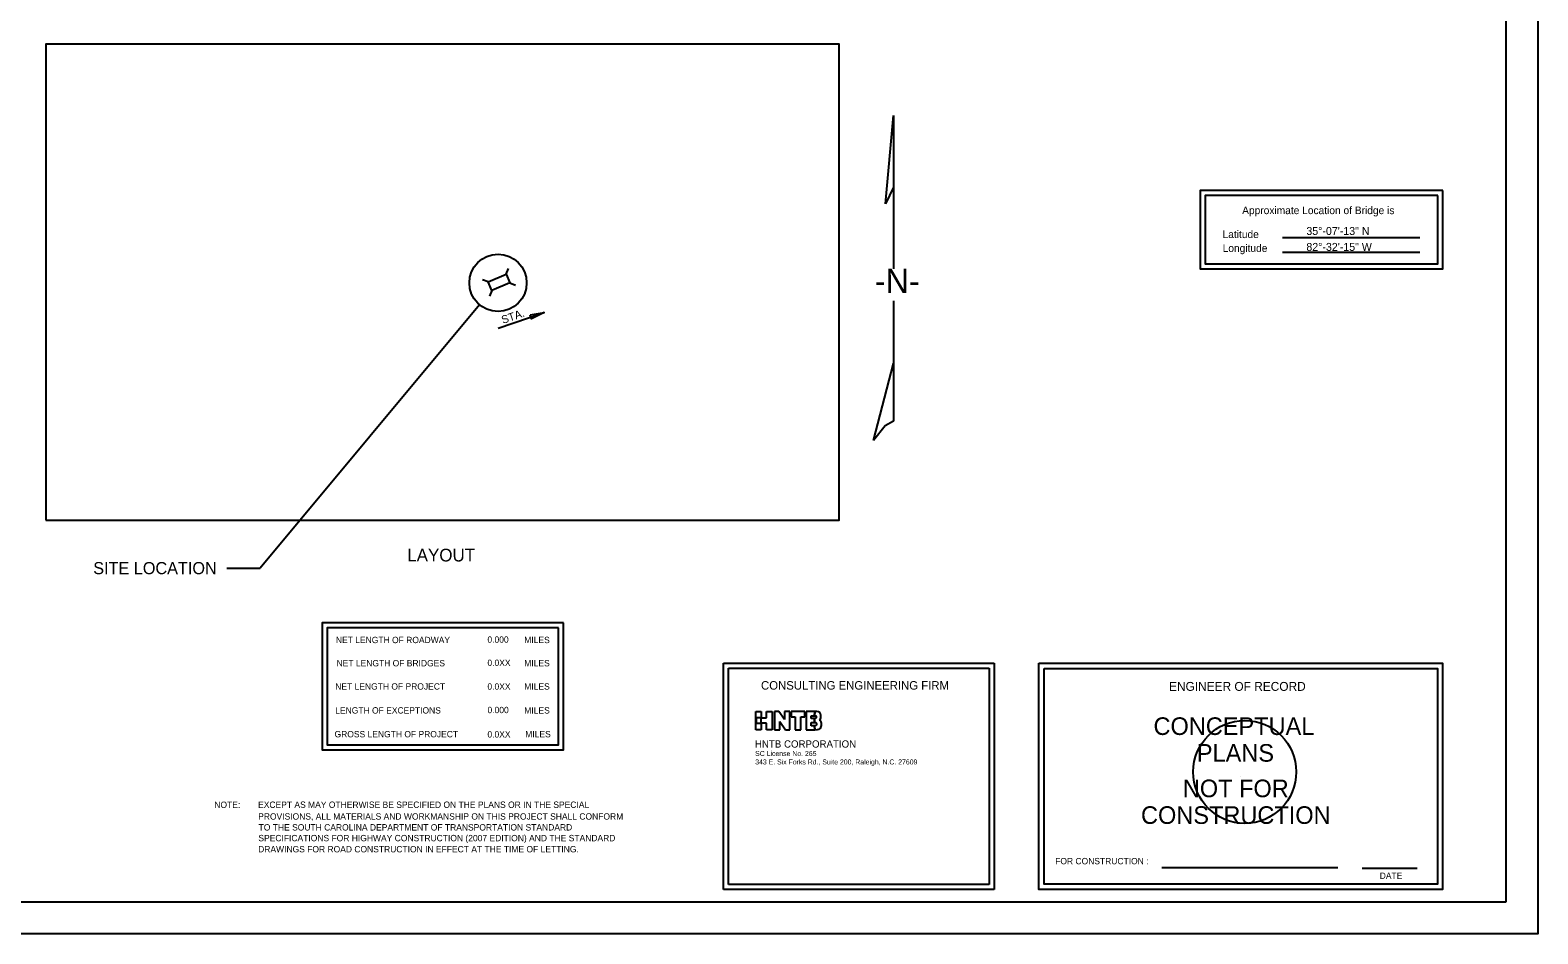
# Model space of a CAD drawing. Extents: x 0 to 4.05, y -2.5 to 2.32.
# Drawn here: x 1.021 to 3, y -2.5 to -1.314 of the extents above; entities that cross this region are included whole.
import ezdxf

# ---------------------------------------------------------------- set-up
doc = ezdxf.new("R2010")
doc.units = 0
for name, color, linetype in [('BR_AUTO DIMENSION', 7, 'Continuous'), ('BR_BORDER LINES', 7, 'Continuous'), ('BR_DETAILS', 7, 'Continuous'), ('BR_TEXT', 7, 'Continuous'), ('Default', 7, 'Continuous'), ('NoPlot', 7, 'Continuous'), ('V7_23', 7, 'Continuous')]:
    doc.layers.add(name, color=color, linetype=linetype)

msp = doc.modelspace()

# ---------------------------------------------------------------- linework, layer by layer
at = {"layer": 'BR_AUTO DIMENSION'}
for p, q in [((2.1436, -1.5418), (2.1542, -1.4259)), ((2.1542, -1.4259), (2.1542, -1.5203)), ((2.1542, -1.5203), (2.1436, -1.5418)), ((2.1542, -1.5203), (2.1542, -1.5857)), ((2.1542, -1.5857), (2.1542, -1.6274)), ((1.6107, -1.6746), (1.3227, -2.02)), ((2.1542, -1.6691), (2.1542, -1.7516)), ((2.1279, -1.8526), (2.1542, -1.7516)), ((2.1542, -1.7516), (2.1542, -1.7641)), ((2.1542, -1.7641), (2.1542, -1.8273)), ((1.2789, -2.02), (1.3227, -2.02)), ((1.931, -2.1449), (2.286, -2.1449)), ((1.931, -2.4416), (1.931, -2.1449)), ((1.9373, -2.1513), (2.2796, -2.1513)), ((1.9373, -2.4352), (1.9373, -2.1513)), ((2.2796, -2.1513), (2.2796, -2.4352)), ((2.286, -2.1449), (2.286, -2.4416)), ((2.286, -2.4416), (1.931, -2.4416)), ((2.2796, -2.4352), (1.9373, -2.4352))]:
    msp.add_line(p, q, dxfattribs=at)
msp.add_lwpolyline([(2.1542, -1.8273), (2.1429, -1.8334), (2.1279, -1.8526)], dxfattribs=at)
msp.add_circle((1.6348, -1.6457), 0.0376, dxfattribs=at)
at = {"layer": 'BR_BORDER LINES'}
for p, q in [((2.9583, -2.4582), (2.9583, -0.7082)), ((2.9583, -1.3928), (2.9583, -0.8053)), ((0.1667, -2.4582), (2.9583, -2.4582))]:
    msp.add_line(p, q, dxfattribs=at)
msp.add_lwpolyline([(1.0411, -1.9573), (2.0828, -1.9573), (2.0828, -1.3323), (1.0411, -1.3323)], close=True, dxfattribs=at)
at = {"layer": 'BR_DETAILS'}
for p, q in [((2.6649, -1.5862), (2.8452, -1.5862)), ((2.6649, -1.6056), (2.8452, -1.6056)), ((2.5063, -2.4129), (2.7373, -2.4129)), ((2.7692, -2.4138), (2.8416, -2.4138))]:
    msp.add_line(p, q, dxfattribs=at)
for points in [[(2.8752, -1.5246), (2.5568, -1.5246), (2.5568, -1.6272), (2.8752, -1.6272)], [(2.8685, -1.5312), (2.5634, -1.5312), (2.5634, -1.6206), (2.8685, -1.6206)], [(2.345, -2.1449), (2.875, -2.1449), (2.875, -2.4416), (2.345, -2.4416)], [(2.3517, -2.1516), (2.8683, -2.1516), (2.8683, -2.4349), (2.3517, -2.4349)]]:
    msp.add_lwpolyline(points, close=True, dxfattribs=at)
at = {"layer": 'BR_TEXT'}
for p, q in [((1.6219, -1.6444), (1.6143, -1.6415)), ((1.6455, -1.6344), (1.6487, -1.6269)), ((1.6267, -1.6558), (1.6235, -1.6632)), ((1.6503, -1.6458), (1.6579, -1.6486)), ((1.6348, -1.7053), (1.6955, -1.6844))]:
    msp.add_line(p, q, dxfattribs=at)
for points in [[(1.6455, -1.6344), (1.6503, -1.6458), (1.6267, -1.6558), (1.6219, -1.6444)], [(1.6769, -1.6878), (1.6955, -1.6844), (1.6788, -1.6931)], [(1.7207, -2.0919), (1.4041, -2.0919), (1.4041, -2.2586), (1.7207, -2.2586)], [(1.7141, -2.0986), (1.4107, -2.0986), (1.4107, -2.2519), (1.7141, -2.2519)]]:
    msp.add_lwpolyline(points, close=True, dxfattribs=at)
at = {"layer": 'Default'}
msp.add_line((2.61, -2.2932), (2.61, -2.2932), dxfattribs=at)
at = {"layer": 'NoPlot'}
msp.add_lwpolyline([(0, -0.6667), (3, -0.6667), (3, -2.5), (0, -2.5)], close=True, dxfattribs=at)
msp.add_circle((2.6152, -2.2875), 0.0676, dxfattribs=at)
at = {"layer": 'V7_23'}
for p, q in [((1.9733, -2.2323), (1.9733, -2.2083)), ((1.9733, -2.2083), (1.9804, -2.2083)), ((1.9804, -2.2164), (1.9736, -2.2164)), ((1.9736, -2.2164), (1.9736, -2.2235)), ((1.9804, -2.2083), (1.9804, -2.2164)), ((1.9804, -2.2235), (1.9804, -2.2164)), ((1.9804, -2.2164), (1.9875, -2.2164)), ((1.9875, -2.2164), (1.9875, -2.2083)), ((1.9875, -2.2083), (1.9946, -2.2083)), ((1.9946, -2.2083), (1.9946, -2.2323)), ((2.0037, -2.2083), (1.9978, -2.2083)), ((1.9978, -2.2083), (1.9978, -2.2323)), ((2.0108, -2.2188), (2.0037, -2.2083)), ((2.0178, -2.2083), (2.0108, -2.2083)), ((2.0108, -2.2083), (2.0108, -2.2188)), ((2.0178, -2.2323), (2.0178, -2.2083)), ((2.0198, -2.2083), (2.0198, -2.2153)), ((2.0375, -2.2083), (2.0198, -2.2083)), ((2.0198, -2.2153), (2.0251, -2.2153)), ((2.0251, -2.2153), (2.0251, -2.2323)), ((2.0322, -2.2323), (2.0322, -2.2153)), ((2.0322, -2.2153), (2.0375, -2.2153)), ((2.0375, -2.2153), (2.0375, -2.2083)), ((2.0507, -2.2083), (2.0396, -2.2083)), ((2.0396, -2.2083), (2.0396, -2.2323)), ((2.0461, -2.2172), (2.0461, -2.2137)), ((2.0461, -2.2137), (2.0503, -2.2137)), ((2.0503, -2.2137), (2.0507, -2.2083)), ((2.0507, -2.2083), (2.0503, -2.2137)), ((1.9804, -2.2323), (1.9733, -2.2323)), ((1.9736, -2.2235), (1.9804, -2.2235)), ((1.9875, -2.2235), (1.9804, -2.2235)), ((1.9804, -2.2235), (1.9804, -2.2323)), ((1.9875, -2.2323), (1.9875, -2.2235)), ((1.9946, -2.2323), (1.9875, -2.2323)), ((1.9978, -2.2323), (2.0048, -2.2323)), ((2.0048, -2.2323), (2.0048, -2.2215)), ((2.0048, -2.2215), (2.0121, -2.2323)), ((2.0121, -2.2323), (2.0178, -2.2323)), ((2.0251, -2.2323), (2.0322, -2.2323)), ((2.0396, -2.2323), (2.0506, -2.2323)), ((2.0505, -2.2172), (2.0461, -2.2172)), ((2.0461, -2.227), (2.0461, -2.2225)), ((2.0461, -2.2225), (2.0502, -2.2225)), ((2.0503, -2.227), (2.0461, -2.227)), ((2.0502, -2.2225), (2.0505, -2.2172)), ((2.0505, -2.2172), (2.0502, -2.2225)), ((2.0506, -2.2323), (2.0503, -2.227)), ((2.0503, -2.227), (2.0506, -2.2323))]:
    msp.add_line(p, q, dxfattribs=at)
for points in [[(2.0503, -2.2137), (2.0522, -2.2137), (2.0524, -2.2149), (2.0524, -2.2155), (2.0524, -2.2161), (2.052, -2.2172), (2.0505, -2.2172)], [(2.0568, -2.2194), (2.0582, -2.2182), (2.0588, -2.2165), (2.0588, -2.2153), (2.0588, -2.211), (2.0557, -2.2083), (2.0507, -2.2083), (2.0507, -2.2083), (2.0507, -2.2083), (2.0506, -2.2083)], [(2.0502, -2.2225), (2.0524, -2.2225), (2.0528, -2.2237), (2.0528, -2.2247), (2.0528, -2.2261), (2.0519, -2.227), (2.0503, -2.227)], [(2.0506, -2.2323), (2.0561, -2.2323), (2.0595, -2.2292), (2.0595, -2.2242), (2.0595, -2.2223), (2.0585, -2.2205), (2.0568, -2.2194)]]:
    msp.add_open_spline(points, degree=3, dxfattribs=at)

# ---------------------------------------------------------------- texts
at = {"layer": 'BR_AUTO DIMENSION'}
for s, p in [('35°-07\'-13" N', (2.6961, -1.5828)), ('82°-32\'-15" W', (2.6961, -1.6037))]:
    msp.add_text(s, height=0.010417, dxfattribs=at).set_placement(p)
msp.add_text('-N-', height=0.03184, rotation=360, dxfattribs=at).set_placement((2.1294, -1.6591))
at = {"layer": 'BR_DETAILS'}
for s, height, p in [('Approximate Location of Bridge is', 0.01, (2.6118, -1.5555)), ('Latitude', 0.01, (2.5861, -1.5869)), ('Longitude', 0.01, (2.5862, -1.6051)), ('LAYOUT', 0.01667, (1.5156, -2.0113)), ('ENGINEER OF RECORD', 0.011667, (2.5158, -2.1811)), ('NOTE:', 0.00833, (1.2624, -2.3348)), ('EXCEPT AS MAY OTHERWISE BE SPECIFIED ON THE PLANS OR IN THE SPECIAL ', 0.008334, (1.3198, -2.3347)), ('PROVISIONS, ALL MATERIALS AND WORKMANSHIP ON THIS PROJECT SHALL CONFORM ', 0.008334, (1.3199, -2.3501)), ('TO THE SOUTH CAROLINA DEPARTMENT OF TRANSPORTATION STANDARD ', 0.008334, (1.3205, -2.3644)), ('SPECIFICATIONS FOR HIGHWAY CONSTRUCTION (2007 EDITION) AND THE STANDARD', 0.008334, (1.3202, -2.3785)), ('DRAWINGS FOR ROAD CONSTRUCTION IN EFFECT AT THE TIME OF LETTING.', 0.008334, (1.3199, -2.3931)), ('FOR CONSTRUCTION :', 0.008333, (2.3663, -2.4087)), ('DATE', 0.00833, (2.7924, -2.4279))]:
    msp.add_text(s, height=height, dxfattribs=at).set_placement(p)
for s, height, p in [('CONCEPTUAL', 0.02311, (2.4954, -2.239)), ('PLANS', 0.02311, (2.5523, -2.2741)), ('NOT FOR', 0.02311, (2.5339, -2.3207)), ('CONSTRUCTION', 0.023108, (2.479, -2.3557))]:
    msp.add_text(s, height=height, rotation=360, dxfattribs=at).set_placement(p)
at = {"layer": 'BR_TEXT'}
for s, height, rotation, p in [('STA.', 0.01042, 19.0112, (1.6414, -1.6996)), ('SITE LOCATION ', 0.015922, 360, (1.1034, -2.028)), ('CONSULTING ENGINEERING FIRM', 0.011145, 0, (1.9801, -2.1795))]:
    msp.add_text(s, height=height, rotation=rotation, dxfattribs=at).set_placement(p)
for s, height, p in [('NET LENGTH OF ROADWAY', 0.008333, (1.422, -2.1185)), ('0.000', 0.00833, (1.6209, -2.118)), ('MILES', 0.00833, (1.6693, -2.1185)), ('NET LENGTH OF BRIDGES', 0.008333, (1.4228, -2.149)), ('0.0XX', 0.00833, (1.6209, -2.1485)), ('MILES', 0.00833, (1.6693, -2.149)), ('NET LENGTH OF PROJECT', 0.008333, (1.4211, -2.1795)), ('0.0XX', 0.00833, (1.6209, -2.1796)), ('MILES', 0.00833, (1.6693, -2.1795)), ('LENGTH OF EXCEPTIONS', 0.008333, (1.4211, -2.2109)), ('0.000', 0.00833, (1.621, -2.2104)), ('MILES', 0.00833, (1.6693, -2.2109)), ('GROSS LENGTH OF PROJECT', 0.008333, (1.4202, -2.2421)), ('0.0XX', 0.00833, (1.6209, -2.2424)), ('MILES', 0.00833, (1.6706, -2.2421)), ('HNTB CORPORATION', 0.009516, (1.9721, -2.2556)), ('SC License No. 265', 0.006558, (1.9724, -2.2666)), ('343 E. Six Forks Rd., Suite 200, Raleigh, N.C. 27609', 0.006558, (1.9725, -2.2777))]:
    msp.add_text(s, height=height, dxfattribs=at).set_placement(p)

doc.saveas('drawing.dxf')
